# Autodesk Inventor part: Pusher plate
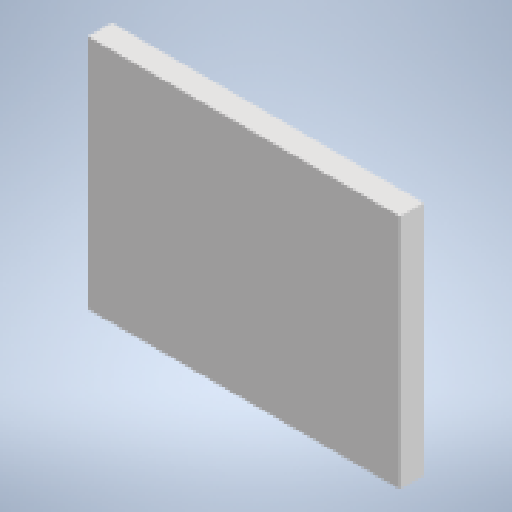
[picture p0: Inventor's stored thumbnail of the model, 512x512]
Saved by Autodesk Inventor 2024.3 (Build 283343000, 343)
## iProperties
Created: 2024-12
Part Number: Pusher plate
Material: Generic
Document SubType Name: Modeling
Designer: ruhr
Density: 1 g/cm^3
Appearance: Default
Author: ruhr
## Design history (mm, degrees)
sketch "Sketch1"
  geometry: L1 (-32.719, 24.768)-(-32.719, -24.768); L2 (-32.719, -24.768)-(32.719, -24.768); L3 (32.719, -24.768)-(32.719, 24.768); L4 (32.719, 24.768)-(-32.719, 24.768); L5 (-32.719, 24.768)-(32.719, -24.768); L6 (-32.719, -24.768)-(32.719, 24.768); 1 further point
  constraints: 12 end point, 2 midpoint, 2 parallel, 1 perpendicular, 1 vertical
extrude "Extrusion1" new body sketch "Sketch1" distance "d0" = 5; taper "d1" = 0 deg
body "Solid1"
